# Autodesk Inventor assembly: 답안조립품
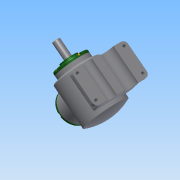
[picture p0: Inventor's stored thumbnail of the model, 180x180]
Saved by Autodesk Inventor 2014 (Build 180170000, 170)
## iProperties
Created: 2018-08
Part Number: 답안조립품
Document SubType Name: Assembly
Designer: 601-06
Author: 601-06
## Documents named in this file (13)
- C:\Users\601-06\Downloads\480808V1020\답안조립품.iam
- C:\Users\601-06\Downloads\480808V1020\본체.ipt
- C:\Users\601-06\Downloads\480808V1020\커버.ipt
- C:\Users\601-06\Downloads\480808V1020\베어링 6203.ipt
- C:\Users\601-06\Downloads\480808V1020\메인 축.ipt
- 메인 축.ipt
- C:\Users\601-06\Downloads\480808V1020\키 5x5.ipt
- C:\Users\601-06\Downloads\480808V1020\메인 베벨기어.ipt
- C:\Users\601-06\Downloads\480808V1020\서브 축.ipt
- 서브 축.ipt
- C:\Users\601-06\Downloads\480808V1020\서브 베벨기어.ipt
- C:\Users\601-06\Downloads\480808V1020\키 4x4.ipt
- C:\Users\601-06\Downloads\480808V1020\볼트 M4.ipt
